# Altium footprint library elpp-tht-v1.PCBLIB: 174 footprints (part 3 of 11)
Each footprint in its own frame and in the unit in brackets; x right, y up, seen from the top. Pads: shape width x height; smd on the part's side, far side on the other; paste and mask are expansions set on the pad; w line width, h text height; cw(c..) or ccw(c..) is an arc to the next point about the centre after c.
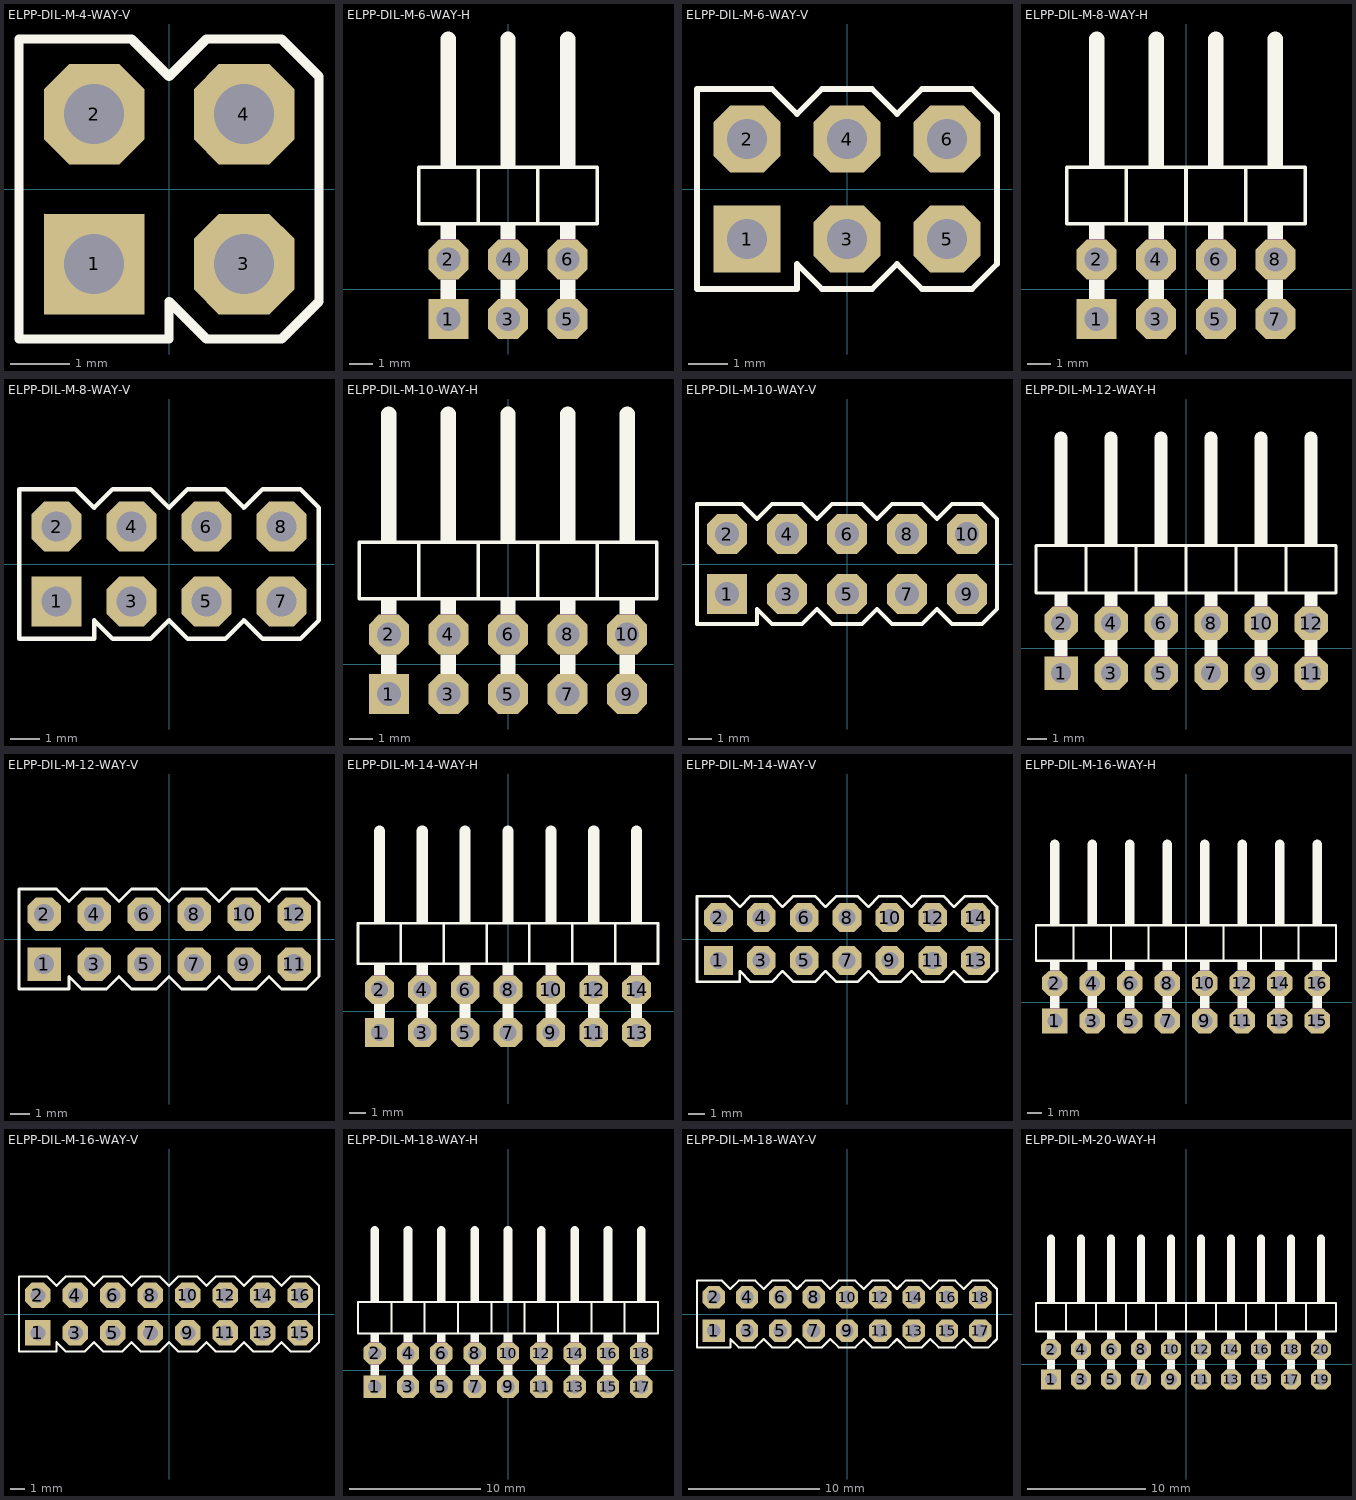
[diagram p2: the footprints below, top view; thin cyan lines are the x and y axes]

## ELPP-DIL-M-4-WAY-V [mil]
pads (4):
  rect 67x67 hole 40: 1(-50,-50)
  oct 67x67 hole 40: 2(-50,50) 3(50,-50) 4(50,50)
Top Overlay:
  lines w6: -100,-100 0,-100 0,-75 25,-100 75,-100 100,-75 100,75 75,100 25,100 0,75 -25,100 -100,100 -100,-100
Mechanical 2:
  text ">NAME" at -100,125 h42.5
Mechanical 4:
  text ">VALUE" at -100,-175 h42.5
Mechanical 16:
  rectangle: 40,-60 60,-40
  rectangle: -60,-60 -40,-40
  rectangle: 40,40 60,60
  rectangle: -60,40 -40,60

## ELPP-DIL-M-6-WAY-H [mil]
pads (6):
  rect 67x67 hole 40: 1(-100,-50)
  oct 67x67 hole 40: 2(-100,50) 3(0,-50) 4(0,50) 5(100,-50) 6(100,50)
Top Overlay:
  rectangle: -113,205 -87,235
  rectangle: -13,205 13,235
  rectangle: 87,205 113,235
  rectangle: 87,84 113,110
  rectangle: -13,84 13,110
  rectangle: -113,84 -87,110
  rectangle: -113,-16 -87,16
  rectangle: -13,-16 13,16
  rectangle: 87,-16 113,16
  lines w6: -50,110 -50,205 ; -50,110 -150,110 -150,205 -50,205 ; -50,110 50,110 ; -50,205 50,205 ; 50,110 150,110 150,205 50,205 ; 50,110 50,205
  lines w26: -100,235 -100,420 ; 0,235 0,420 ; 100,235 100,420
Mechanical 2:
  text ">NAME" at -175,175 h42.5
Mechanical 4:
  text ">VALUE" at 175,125 h42.5
Mechanical 16:
  rectangle: -113,16 -87,84
  rectangle: -113,-62 -87,-16
  rectangle: -13,16 13,84
  rectangle: -13,-62 13,-16
  rectangle: 87,16 113,84
  rectangle: 87,-62 113,-16

## ELPP-DIL-M-6-WAY-V [mil]
pads (6):
  rect 67x67 hole 40: 1(-100,-50)
  oct 67x67 hole 40: 2(-100,50) 3(0,-50) 4(0,50) 5(100,-50) 6(100,50)
Top Overlay:
  lines w6: -150,-100 -50,-100 -50,-75 -25,-100 25,-100 50,-75 75,-100 125,-100 150,-75 150,75 125,100 75,100 50,75 25,100 -25,100 -50,75 -75,100 -150,100 -150,-100
Mechanical 2:
  text ">NAME" at -150,125 h42.5
Mechanical 4:
  text ">VALUE" at -150,-175 h42.5
Mechanical 16:
  rectangle: -10,-60 10,-40
  rectangle: -110,-60 -90,-40
  rectangle: 90,-60 110,-40
  rectangle: -10,40 10,60
  rectangle: -110,40 -90,60
  rectangle: 90,40 110,60

## ELPP-DIL-M-8-WAY-H [mil]
pads (8):
  rect 67x67 hole 40: 1(-150,-50)
  oct 67x67 hole 40: 2(-150,50) 3(-50,-50) 4(-50,50) 5(50,-50) 6(50,50) 7(150,-50) 8(150,50)
Top Overlay:
  rectangle: -163,205 -137,235
  rectangle: -63,205 -37,235
  rectangle: 37,205 63,235
  rectangle: 137,205 163,235
  rectangle: 137,84 163,110
  rectangle: 37,84 63,110
  rectangle: -63,84 -37,110
  rectangle: -163,84 -137,110
  rectangle: -163,-16 -137,16
  rectangle: -63,-16 -37,16
  rectangle: 37,-16 63,16
  rectangle: 137,-16 163,16
  lines w6: -100,110 -100,205 ; -100,110 -200,110 -200,205 -100,205 ; -100,110 0,110 ; -100,205 0,205 ; 0,110 100,110 ; 0,110 0,205 ; 0,205 100,205 ; 100,110 200,110 200,205 100,205 ; 100,110 100,205
  lines w26: -150,235 -150,420 ; -50,235 -50,420 ; 50,235 50,420 ; 150,235 150,420
Mechanical 2:
  text ">NAME" at -225,175 h42.5
Mechanical 4:
  text ">VALUE" at 225,125 h42.5
Mechanical 16:
  rectangle: -163,16 -137,84
  rectangle: -163,-62 -137,-16
  rectangle: -63,16 -37,84
  rectangle: -63,-62 -37,-16
  rectangle: 37,16 63,84
  rectangle: 37,-62 63,-16
  rectangle: 137,16 163,84
  rectangle: 137,-62 163,-16

## ELPP-DIL-M-8-WAY-V [mil]
pads (8):
  rect 67x67 hole 40: 1(-150,-50)
  oct 67x67 hole 40: 2(-150,50) 3(-50,-50) 4(-50,50) 5(50,-50) 6(50,50) 7(150,-50) 8(150,50)
Top Overlay:
  lines w6: -200,-100 -100,-100 -100,-75 -75,-100 -25,-100 0,-75 25,-100 75,-100 100,-75 125,-100 175,-100 200,-75 200,75 175,100 125,100 100,75 75,100 25,100 0,75 -25,100 -75,100 -100,75 -125,100 -200,100 -200,-100
Mechanical 2:
  text ">NAME" at -200,125 h42.5
Mechanical 4:
  text ">VALUE" at -200,-175 h42.5
Mechanical 16:
  rectangle: -60,-60 -40,-40
  rectangle: -160,-60 -140,-40
  rectangle: 40,-60 60,-40
  rectangle: 140,-60 160,-40
  rectangle: -60,40 -40,60
  rectangle: -160,40 -140,60
  rectangle: 40,40 60,60
  rectangle: 140,40 160,60

## ELPP-DIL-M-10-WAY-H [mil]
pads (10):
  rect 67x67 hole 40: 1(-200,-50)
  oct 67x67 hole 40: 2(-200,50) 3(-100,-50) 4(-100,50) 5(0,-50) 6(0,50) 7(100,-50) 8(100,50) 9(200,-50) 10(200,50)
Top Overlay:
  rectangle: -213,205 -187,235
  rectangle: -113,205 -87,235
  rectangle: -13,205 13,235
  rectangle: 87,205 113,235
  rectangle: 187,205 213,235
  rectangle: 187,84 213,110
  rectangle: 87,84 113,110
  rectangle: -13,84 13,110
  rectangle: -113,84 -87,110
  rectangle: -213,84 -187,110
  rectangle: -213,-16 -187,16
  rectangle: -113,-16 -87,16
  rectangle: -13,-16 13,16
  rectangle: 87,-16 113,16
  rectangle: 187,-16 213,16
  lines w6: -150,110 -150,205 ; -150,110 -250,110 -250,205 -150,205 ; -150,110 -50,110 ; -150,205 -50,205 ; -50,110 50,110 ; -50,110 -50,205 ; -50,205 50,205 ; 50,110 150,110 ; 50,110 50,205 ; 50,205 150,205 ; 150,110 250,110 250,205 150,205 ; 150,110 150,205
  lines w26: -200,235 -200,420 ; -100,235 -100,420 ; 0,235 0,420 ; 100,235 100,420 ; 200,235 200,420
Mechanical 2:
  text ">NAME" at -275,175 h42.5
Mechanical 4:
  text ">VALUE" at 275,125 h42.5
Mechanical 16:
  rectangle: -213,16 -187,84
  rectangle: -213,-62 -187,-16
  rectangle: -113,16 -87,84
  rectangle: -113,-62 -87,-16
  rectangle: -13,16 13,84
  rectangle: -13,-62 13,-16
  rectangle: 87,16 113,84
  rectangle: 87,-62 113,-16
  rectangle: 187,16 213,84
  rectangle: 187,-62 213,-16

## ELPP-DIL-M-10-WAY-V [mil]
pads (10):
  rect 67x67 hole 40: 1(-200,-50)
  oct 67x67 hole 40: 2(-200,50) 3(-100,-50) 4(-100,50) 5(0,-50) 6(0,50) 7(100,-50) 8(100,50) 9(200,-50) 10(200,50)
Top Overlay:
  lines w6: -250,-100 -150,-100 -150,-75 -125,-100 -75,-100 -50,-75 -25,-100 25,-100 50,-75 75,-100 125,-100 150,-75 175,-100 225,-100 250,-75 250,75 225,100 175,100 150,75 125,100 75,100 50,75 25,100 -25,100 -50,75 -75,100 -125,100 -150,75 -175,100 -250,100 -250,-100
Mechanical 2:
  text ">NAME" at -250,125 h42.5
Mechanical 4:
  text ">VALUE" at -250,-175 h42.5
Mechanical 16:
  rectangle: -110,-60 -90,-40
  rectangle: -210,-60 -190,-40
  rectangle: -10,-60 10,-40
  rectangle: 190,-60 210,-40
  rectangle: 90,-60 110,-40
  rectangle: -110,40 -90,60
  rectangle: -210,40 -190,60
  rectangle: -10,40 10,60
  rectangle: 190,40 210,60
  rectangle: 90,40 110,60

## ELPP-DIL-M-12-WAY-H [mil]
pads (12):
  rect 67x67 hole 40: 1(-250,-50)
  oct 67x67 hole 40: 2(-250,50) 3(-150,-50) 4(-150,50) 5(-50,-50) 6(-50,50) 7(50,-50) 8(50,50) 9(150,-50) 10(150,50) 11(250,-50) 12(250,50)
Top Overlay:
  rectangle: 237,205 263,235
  rectangle: -263,205 -237,235
  rectangle: -163,205 -137,235
  rectangle: -63,205 -37,235
  rectangle: 37,205 63,235
  rectangle: 137,205 163,235
  rectangle: 237,84 263,110
  rectangle: 137,84 163,110
  rectangle: 37,84 63,110
  rectangle: -63,84 -37,110
  rectangle: -163,84 -137,110
  rectangle: -263,84 -237,110
  rectangle: -263,-16 -237,16
  rectangle: -163,-16 -137,16
  rectangle: -63,-16 -37,16
  rectangle: 37,-16 63,16
  rectangle: 137,-16 163,16
  rectangle: 237,-16 263,16
  lines w6: -200,110 -200,205 ; -200,110 -300,110 -300,205 -200,205 ; -200,110 -100,110 ; -200,205 -100,205 ; -100,110 0,110 ; -100,110 -100,205 ; -100,205 0,205 ; 0,110 100,110 ; 0,110 0,205 ; 0,205 100,205 ; 100,110 200,110 ; 100,110 100,205 ; 100,205 200,205 ; 200,110 300,110 300,205 200,205 ; 200,110 200,205
  lines w26: -250,235 -250,420 ; -150,235 -150,420 ; -50,235 -50,420 ; 50,235 50,420 ; 150,235 150,420 ; 250,235 250,420
Mechanical 2:
  text ">NAME" at -325,175 h42.5
Mechanical 4:
  text ">VALUE" at 325,125 h42.5
Mechanical 16:
  rectangle: -263,16 -237,84
  rectangle: -263,-62 -237,-16
  rectangle: -163,16 -137,84
  rectangle: -163,-62 -137,-16
  rectangle: -63,16 -37,84
  rectangle: -63,-62 -37,-16
  rectangle: 37,16 63,84
  rectangle: 37,-62 63,-16
  rectangle: 137,16 163,84
  rectangle: 237,16 263,84
  rectangle: 137,-62 163,-16
  rectangle: 237,-62 263,-16

## ELPP-DIL-M-12-WAY-V [mil]
pads (12):
  rect 67x67 hole 40: 1(-250,-50)
  oct 67x67 hole 40: 2(-250,50) 3(-150,-50) 4(-150,50) 5(-50,-50) 6(-50,50) 7(50,-50) 8(50,50) 9(150,-50) 10(150,50) 11(250,-50) 12(250,50)
Top Overlay:
  lines w6: -300,-100 -200,-100 -200,-75 -175,-100 -125,-100 -100,-75 -75,-100 -25,-100 0,-75 25,-100 75,-100 100,-75 125,-100 175,-100 200,-75 225,-100 275,-100 300,-75 300,75 275,100 225,100 200,75 175,100 125,100 100,75 75,100 25,100 0,75 -25,100 -75,100 -100,75 -125,100 -175,100 -200,75 -225,100 -300,100 -300,-100
Mechanical 2:
  text ">NAME" at -300,125 h42.5
Mechanical 4:
  text ">VALUE" at -300,-175 h42.5
Mechanical 16:
  rectangle: -160,-60 -140,-40
  rectangle: -260,-60 -240,-40
  rectangle: -60,-60 -40,-40
  rectangle: 140,-60 160,-40
  rectangle: 40,-60 60,-40
  rectangle: 240,-60 260,-40
  rectangle: -160,40 -140,60
  rectangle: -260,40 -240,60
  rectangle: -60,40 -40,60
  rectangle: 140,40 160,60
  rectangle: 40,40 60,60
  rectangle: 240,40 260,60

## ELPP-DIL-M-14-WAY-H [mil]
pads (14):
  rect 67x67 hole 40: 1(-300,-50)
  oct 67x67 hole 40: 2(-300,50) 3(-200,-50) 4(-200,50) 5(-100,-50) 6(-100,50) 7(0,-50) 8(0,50) 9(100,-50) 10(100,50) 11(200,-50) 12(200,50) 13(300,-50) 14(300,50)
Top Overlay:
  rectangle: 187,205 213,235
  rectangle: 287,205 313,235
  rectangle: -313,205 -287,235
  rectangle: -213,205 -187,235
  rectangle: -113,205 -87,235
  rectangle: -13,205 13,235
  rectangle: 87,205 113,235
  rectangle: 287,84 313,110
  rectangle: 187,84 213,110
  rectangle: 87,84 113,110
  rectangle: -13,84 13,110
  rectangle: -113,84 -87,110
  rectangle: -213,84 -187,110
  rectangle: -313,84 -287,110
  rectangle: -313,-16 -287,16
  rectangle: -213,-16 -187,16
  rectangle: -113,-16 -87,16
  rectangle: -13,-16 13,16
  rectangle: 87,-16 113,16
  rectangle: 187,-16 213,16
  rectangle: 287,-16 313,16
  lines w6: -250,110 -250,205 ; -250,110 -350,110 -350,205 -250,205 ; -250,110 -150,110 ; -250,205 -150,205 ; -150,110 -50,110 ; -150,110 -150,205 ; -150,205 -50,205 ; -50,110 50,110 ; -50,110 -50,205 ; -50,205 50,205 ; 50,110 150,110 ; 50,110 50,205 ; 50,205 150,205 ; 150,110 250,110 ; 150,110 150,205 ; 150,205 250,205 ; 250,110 250,205 ; 250,110 350,110 350,205 250,205
  lines w26: -300,235 -300,420 ; -200,235 -200,420 ; -100,235 -100,420 ; 0,235 0,420 ; 100,235 100,420 ; 200,235 200,420 ; 300,235 300,420
Mechanical 2:
  text ">NAME" at -375,175 h42.5
Mechanical 4:
  text ">VALUE" at 375,125 h42.5
Mechanical 16:
  rectangle: -313,16 -287,84
  rectangle: -313,-62 -287,-16
  rectangle: -213,16 -187,84
  rectangle: -213,-62 -187,-16
  rectangle: -113,16 -87,84
  rectangle: -113,-62 -87,-16
  rectangle: -13,16 13,84
  rectangle: -13,-62 13,-16
  rectangle: 87,16 113,84
  rectangle: 187,16 213,84
  rectangle: 87,-62 113,-16
  rectangle: 187,-62 213,-16
  rectangle: 287,16 313,84
  rectangle: 287,-62 313,-16

## ELPP-DIL-M-14-WAY-V [mil]
pads (14):
  rect 67x67 hole 40: 1(-300,-50)
  oct 67x67 hole 40: 2(-300,50) 3(-200,-50) 4(-200,50) 5(-100,-50) 6(-100,50) 7(0,-50) 8(0,50) 9(100,-50) 10(100,50) 11(200,-50) 12(200,50) 13(300,-50) 14(300,50)
Top Overlay:
  lines w6: -350,-100 -250,-100 -250,-75 -225,-100 -175,-100 -150,-75 -125,-100 -75,-100 -50,-75 -25,-100 25,-100 50,-75 75,-100 125,-100 150,-75 175,-100 225,-100 250,-75 275,-100 325,-100 350,-75 350,75 325,100 275,100 250,75 225,100 175,100 150,75 125,100 75,100 50,75 25,100 -25,100 -50,75 -75,100 -125,100 -150,75 -175,100 -225,100 -250,75 -275,100 -350,100 -350,-100
Mechanical 2:
  text ">NAME" at -350,125 h42.5
Mechanical 4:
  text ">VALUE" at -350,-175 h42.5
Mechanical 16:
  rectangle: -210,-60 -190,-40
  rectangle: -310,-60 -290,-40
  rectangle: -110,-60 -90,-40
  rectangle: 90,-60 110,-40
  rectangle: -10,-60 10,-40
  rectangle: 190,-60 210,-40
  rectangle: 290,-60 310,-40
  rectangle: -210,40 -190,60
  rectangle: -310,40 -290,60
  rectangle: -110,40 -90,60
  rectangle: 90,40 110,60
  rectangle: -10,40 10,60
  rectangle: 190,40 210,60
  rectangle: 290,40 310,60

## ELPP-DIL-M-16-WAY-H [mil]
pads (16):
  rect 67x67 hole 40: 1(-350,-50)
  oct 67x67 hole 40: 2(-350,50) 3(-250,-50) 4(-250,50) 5(-150,-50) 6(-150,50) 7(-50,-50) 8(-50,50) 9(50,-50) 10(50,50) 11(150,-50) 12(150,50) 13(250,-50) 14(250,50) 15(350,-50) 16(350,50)
Top Overlay:
  rectangle: 137,205 163,235
  rectangle: 237,205 263,235
  rectangle: 337,205 363,235
  rectangle: -363,205 -337,235
  rectangle: -263,205 -237,235
  rectangle: -163,205 -137,235
  rectangle: -63,205 -37,235
  rectangle: 37,205 63,235
  rectangle: 337,84 363,110
  rectangle: 237,84 263,110
  rectangle: 137,84 163,110
  rectangle: 37,84 63,110
  rectangle: -63,84 -37,110
  rectangle: -163,84 -137,110
  rectangle: -263,84 -237,110
  rectangle: -363,84 -337,110
  rectangle: -363,-16 -337,16
  rectangle: -263,-16 -237,16
  rectangle: -163,-16 -137,16
  rectangle: -63,-16 -37,16
  rectangle: 37,-16 63,16
  rectangle: 137,-16 163,16
  rectangle: 237,-16 263,16
  rectangle: 337,-16 363,16
  lines w6: -300,110 -300,205 ; -300,110 -400,110 -400,205 -300,205 ; -300,110 -200,110 ; -300,205 -200,205 ; -200,110 -100,110 ; -200,110 -200,205 ; -200,205 -100,205 ; -100,110 0,110 ; -100,110 -100,205 ; -100,205 0,205 ; 0,110 100,110 ; 0,110 0,205 ; 0,205 100,205 ; 100,110 200,110 ; 100,110 100,205 ; 100,205 200,205 ; 200,110 200,205 ; 200,110 300,110 ; 200,205 300,205 ; 300,110 400,110 400,205 300,205 ; 300,110 300,205
  lines w26: -350,235 -350,420 ; -250,235 -250,420 ; -150,235 -150,420 ; -50,235 -50,420 ; 50,235 50,420 ; 150,235 150,420 ; 250,235 250,420 ; 350,235 350,420
Mechanical 2:
  text ">NAME" at -425,175 h42.5
Mechanical 4:
  text ">VALUE" at 425,125 h42.5
Mechanical 16:
  rectangle: -363,16 -337,84
  rectangle: -363,-62 -337,-16
  rectangle: -263,16 -237,84
  rectangle: -263,-62 -237,-16
  rectangle: -163,16 -137,84
  rectangle: -163,-62 -137,-16
  rectangle: -63,16 -37,84
  rectangle: -63,-62 -37,-16
  rectangle: 37,16 63,84
  rectangle: 137,16 163,84
  rectangle: 37,-62 63,-16
  rectangle: 137,-62 163,-16
  rectangle: 237,16 263,84
  rectangle: 237,-62 263,-16
  rectangle: 337,16 363,84
  rectangle: 337,-62 363,-16

## ELPP-DIL-M-16-WAY-V [mil]
pads (16):
  rect 67x67 hole 40: 1(-350,-50)
  oct 67x67 hole 40: 2(-350,50) 3(-250,-50) 4(-250,50) 5(-150,-50) 6(-150,50) 7(-50,-50) 8(-50,50) 9(50,-50) 10(50,50) 11(150,-50) 12(150,50) 13(250,-50) 14(250,50) 15(350,-50) 16(350,50)
Top Overlay:
  lines w6: -400,-100 -300,-100 -300,-75 -275,-100 -225,-100 -200,-75 -175,-100 -125,-100 -100,-75 -75,-100 -25,-100 0,-75 25,-100 75,-100 100,-75 125,-100 175,-100 200,-75 225,-100 275,-100 300,-75 325,-100 375,-100 400,-75 400,75 375,100 325,100 300,75 275,100 225,100 200,75 175,100 125,100 100,75 75,100 25,100 0,75 -25,100 -75,100 -100,75 -125,100 -175,100 -200,75 -225,100 -275,100 -300,75 -325,100 -400,100 -400,-100
Mechanical 2:
  text ">NAME" at -400,125 h42.5
Mechanical 4:
  text ">VALUE" at -400,-175 h42.5
Mechanical 16:
  rectangle: -260,-60 -240,-40
  rectangle: -360,-60 -340,-40
  rectangle: -160,-60 -140,-40
  rectangle: 40,-60 60,-40
  rectangle: -60,-60 -40,-40
  rectangle: 140,-60 160,-40
  rectangle: 240,-60 260,-40
  rectangle: 340,-60 360,-40
  rectangle: -260,40 -240,60
  rectangle: -360,40 -340,60
  rectangle: -160,40 -140,60
  rectangle: 40,40 60,60
  rectangle: -60,40 -40,60
  rectangle: 140,40 160,60
  rectangle: 240,40 260,60
  rectangle: 340,40 360,60

## ELPP-DIL-M-18-WAY-H [mil]
pads (18):
  rect 67x67 hole 40: 1(-400,-50)
  oct 67x67 hole 40: 2(-400,50) 3(-300,-50) 4(-300,50) 5(-200,-50) 6(-200,50) 7(-100,-50) 8(-100,50) 9(0,-50) 10(0,50) 11(100,-50) 12(100,50) 13(200,-50) 14(200,50) 15(300,-50) 16(300,50) 17(400,-50) 18(400,50)
Top Overlay:
  rectangle: 87,205 113,235
  rectangle: 187,205 213,235
  rectangle: 287,205 313,235
  rectangle: 387,205 413,235
  rectangle: -413,205 -387,235
  rectangle: -313,205 -287,235
  rectangle: -213,205 -187,235
  rectangle: -113,205 -87,235
  rectangle: -13,205 13,235
  rectangle: 387,84 413,110
  rectangle: 287,84 313,110
  rectangle: 187,84 213,110
  rectangle: 87,84 113,110
  rectangle: -13,84 13,110
  rectangle: -113,84 -87,110
  rectangle: -213,84 -187,110
  rectangle: -313,84 -287,110
  rectangle: -413,84 -387,110
  rectangle: -413,-16 -387,16
  rectangle: -313,-16 -287,16
  rectangle: -213,-16 -187,16
  rectangle: -113,-16 -87,16
  rectangle: -13,-16 13,16
  rectangle: 87,-16 113,16
  rectangle: 187,-16 213,16
  rectangle: 287,-16 313,16
  rectangle: 387,-16 413,16
  lines w6: -350,110 -350,205 ; -350,110 -450,110 -450,205 -350,205 ; -350,110 -250,110 ; -350,205 -250,205 ; -250,110 -150,110 ; -250,110 -250,205 ; -250,205 -150,205 ; -150,110 -50,110 ; -150,110 -150,205 ; -150,205 -50,205 ; -50,110 50,110 ; -50,110 -50,205 ; -50,205 50,205 ; 50,110 150,110 ; 50,110 50,205 ; 50,205 150,205 ; 150,110 150,205 ; 150,110 250,110 ; 150,205 250,205 ; 250,110 350,110 ; 250,110 250,205 ; 250,205 350,205 ; 350,110 450,110 450,205 350,205 ; 350,110 350,205
  lines w26: -400,235 -400,420 ; -300,235 -300,420 ; -200,235 -200,420 ; -100,235 -100,420 ; 0,235 0,420 ; 100,235 100,420 ; 200,235 200,420 ; 300,235 300,420 ; 400,235 400,420
Mechanical 2:
  text ">NAME" at -475,175 h42.5
Mechanical 4:
  text ">VALUE" at 475,125 h42.5
Mechanical 16:
  rectangle: -413,16 -387,84
  rectangle: -413,-62 -387,-16
  rectangle: -313,16 -287,84
  rectangle: -313,-62 -287,-16
  rectangle: -213,16 -187,84
  rectangle: -213,-62 -187,-16
  rectangle: -113,16 -87,84
  rectangle: -113,-62 -87,-16
  rectangle: -13,16 13,84
  rectangle: 87,16 113,84
  rectangle: -13,-62 13,-16
  rectangle: 87,-62 113,-16
  rectangle: 187,16 213,84
  rectangle: 187,-62 213,-16
  rectangle: 287,16 313,84
  rectangle: 287,-62 313,-16
  rectangle: 387,16 413,84
  rectangle: 387,-62 413,-16

## ELPP-DIL-M-18-WAY-V [mil]
pads (18):
  rect 67x67 hole 40: 1(-400,-50)
  oct 67x67 hole 40: 2(-400,50) 3(-300,-50) 4(-300,50) 5(-200,-50) 6(-200,50) 7(-100,-50) 8(-100,50) 9(0,-50) 10(0,50) 11(100,-50) 12(100,50) 13(200,-50) 14(200,50) 15(300,-50) 16(300,50) 17(400,-50) 18(400,50)
Top Overlay:
  lines w6: -450,-100 -350,-100 -350,-75 -325,-100 -275,-100 -250,-75 -225,-100 -175,-100 -150,-75 -125,-100 -75,-100 -50,-75 -25,-100 25,-100 50,-75 75,-100 125,-100 150,-75 175,-100 225,-100 250,-75 275,-100 325,-100 350,-75 375,-100 425,-100 450,-75 450,75 425,100 375,100 350,75 325,100 275,100 250,75 225,100 175,100 150,75 125,100 75,100 50,75 25,100 -25,100 -50,75 -75,100 -125,100 -150,75 -175,100 -225,100 -250,75 -275,100 -325,100 -350,75 -375,100 -450,100 -450,-100
Mechanical 2:
  text ">NAME" at -450,125 h42.5
Mechanical 4:
  text ">VALUE" at -450,-175 h42.5
Mechanical 16:
  rectangle: -310,-60 -290,-40
  rectangle: -410,-60 -390,-40
  rectangle: -210,-60 -190,-40
  rectangle: -10,-60 10,-40
  rectangle: -110,-60 -90,-40
  rectangle: 90,-60 110,-40
  rectangle: 190,-60 210,-40
  rectangle: 290,-60 310,-40
  rectangle: 390,-60 410,-40
  rectangle: -310,40 -290,60
  rectangle: -410,40 -390,60
  rectangle: -210,40 -190,60
  rectangle: -10,40 10,60
  rectangle: -110,40 -90,60
  rectangle: 90,40 110,60
  rectangle: 190,40 210,60
  rectangle: 290,40 310,60
  rectangle: 390,40 410,60

## ELPP-DIL-M-20-WAY-H [mil]
pads (20):
  rect 67x67 hole 40: 1(-450,-50)
  oct 67x67 hole 40: 2(-450,50) 3(-350,-50) 4(-350,50) 5(-250,-50) 6(-250,50) 7(-150,-50) 8(-150,50) 9(-50,-50) 10(-50,50) 11(50,-50) 12(50,50) 13(150,-50) 14(150,50) 15(250,-50) 16(250,50) 17(350,-50) 18(350,50) 19(450,-50) 20(450,50)
Top Overlay:
  rectangle: 37,205 63,235
  rectangle: 137,205 163,235
  rectangle: 237,205 263,235
  rectangle: 337,205 363,235
  rectangle: 437,205 463,235
  rectangle: -463,205 -437,235
  rectangle: -363,205 -337,235
  rectangle: -263,205 -237,235
  rectangle: -163,205 -137,235
  rectangle: -63,205 -37,235
  rectangle: 437,84 463,110
  rectangle: 337,84 363,110
  rectangle: 237,84 263,110
  rectangle: 137,84 163,110
  rectangle: 37,84 63,110
  rectangle: -63,84 -37,110
  rectangle: -163,84 -137,110
  rectangle: -263,84 -237,110
  rectangle: -363,84 -337,110
  rectangle: -463,84 -437,110
  rectangle: -463,-16 -437,16
  rectangle: -363,-16 -337,16
  rectangle: -263,-16 -237,16
  rectangle: -163,-16 -137,16
  rectangle: -63,-16 -37,16
  rectangle: 37,-16 63,16
  rectangle: 137,-16 163,16
  rectangle: 237,-16 263,16
  rectangle: 337,-16 363,16
  rectangle: 437,-16 463,16
  lines w6: -400,110 -400,205 ; -400,110 -500,110 -500,205 -400,205 ; -400,110 -300,110 ; -400,205 -300,205 ; -300,110 -200,110 ; -300,110 -300,205 ; -300,205 -200,205 ; -200,110 -100,110 ; -200,110 -200,205 ; -200,205 -100,205 ; -100,110 0,110 ; -100,110 -100,205 ; -100,205 0,205 ; 0,110 100,110 ; 0,110 0,205 ; 0,205 100,205 ; 100,110 100,205 ; 100,110 200,110 ; 100,205 200,205 ; 200,110 300,110 ; 200,110 200,205 ; 200,205 300,205 ; 300,110 400,110 ; 300,110 300,205 ; 300,205 400,205 ; 400,110 500,110 500,205 400,205 ; 400,110 400,205
  lines w26: -450,235 -450,420 ; -350,235 -350,420 ; -250,235 -250,420 ; -150,235 -150,420 ; -50,235 -50,420 ; 50,235 50,420 ; 150,235 150,420 ; 250,235 250,420 ; 350,235 350,420 ; 450,235 450,420
Mechanical 2:
  text ">NAME" at -525,175 h42.5
Mechanical 4:
  text ">VALUE" at 525,125 h42.5
Mechanical 16:
  rectangle: -463,16 -437,84
  rectangle: -463,-62 -437,-16
  rectangle: -363,16 -337,84
  rectangle: -363,-62 -337,-16
  rectangle: -263,16 -237,84
  rectangle: -263,-62 -237,-16
  rectangle: -163,16 -137,84
  rectangle: -163,-62 -137,-16
  rectangle: -63,16 -37,84
  rectangle: 37,16 63,84
  rectangle: -63,-62 -37,-16
  rectangle: 37,-62 63,-16
  rectangle: 137,16 163,84
  rectangle: 137,-62 163,-16
  rectangle: 237,16 263,84
  rectangle: 237,-62 263,-16
  rectangle: 337,16 363,84
  rectangle: 437,16 463,84
  rectangle: 337,-62 363,-16
  rectangle: 437,-62 463,-16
